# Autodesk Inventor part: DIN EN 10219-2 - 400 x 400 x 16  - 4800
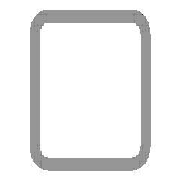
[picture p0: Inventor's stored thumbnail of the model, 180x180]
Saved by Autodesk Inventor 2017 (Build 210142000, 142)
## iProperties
IsCustomPart: 1
Created: 2017-11
Part Number: DIN EN 10219-2 - 400 x 400 x 16  - 4800
Material: Steel, Mild
Description: Cold formed welded structural hollow sections of non-alloy and fine grain structural steel
Document SubType Name: Modeling
Standard: DIN
Designer: iusti
Standard Revision: 2006-07
Standards Organization: DIN
Language: en-US
Size Designation: 400 x 400 x 16
Categories: <MemberInstance><Categories><Category DisplayName="Structural Shapes" InternalName="089c4875-fa83-4c05-b084-43b9cc11f5ed" Mnemonic="GRDR"><CategoryParameter Dis
Stock Number: 400 x 400 x 16
Density: 7.85 g/cm^3
Appearance: Semi-Polished
Mass: 884622 g
Surface Area: 141333 cm^2
Volume: 112691 cm^3
_CCFamilyMember: 142
_CCFamilyDisplayName: DIN EN 10219-2 (Square Hollow Section - Cold Formed) - Cold formed welded structural hollow sections of non-alloy and fine grain structural steel
_FrameMemberDoc: Frame Member File
_Version: 15.0.0
_GetPNFromCC: 1
G_L: 4800.000 mm
G_W: 400.000 mm
G_H: 400.000 mm
+64C0199E-E4A6-42EE-BAB6-C57CBAF8A212+CUTDETAIL1: Cut
Author: iusti
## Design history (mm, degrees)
node "Start plane"
node "End plane"
sketch "Sketch"
  geometry: L1 (-200, -152)-(-200, 152); L2 (-152, 200)-(152, 200); L3 (200, 152)-(200, -152); L4 (152, -200)-(-152, -200); L5 (-152, 184)-(152, 184); L6 (184, 152)-(184, -152); L7 (152, -184)-(-152, -184); L8 (-184, -152)-(-184, 152); L9 (0, 293.918)-(0, -293.918) reference; L10 (-293.918, 0)-(293.918, 0) reference; A1 r 48 centre (-152, -152) between (-200, -152) and (-152, -200); A2 r 48 centre (-152, 152) between (-152, 200) and (-200, 152); A3 r 48 centre (152, 152) between (200, 152) and (152, 200); A4 r 48 centre (152, -152) between (152, -200) and (200, -152); A5 r 32 centre (-152, 152) between (-152, 184) and (-184, 152); A6 r 32 centre (152, 152) between (184, 152) and (152, 184); A7 r 32 centre (152, -152) between (152, -184) and (184, -152); A8 r 32 centre (-152, -152) between (-184, -152) and (-152, -184)
  constraints: 16 end point, 16 point on circle, 8 centre point, 8 tangent, 4 parallel, 3 equal radius, 2 perpendicular, 7 other
  dimensions: "d7" = 48 radius of A1 (= G_IR); "d10" = 400 distance between parallel lines of L2 L4 (= G_H); "d11" = 400 distance between parallel lines of L1 L3 (= G_W); "d12" = 16 distance between parallel lines of L3 L6 (= G_T); "d15" = 200 distance between parallel lines of L2 L10 (= 0.5 x d10); "d16" = 200 distance between parallel lines of L9 L3 (= 0.5 x d11)
extrude "Body" new body sketch "Sketch" stored distance "d3" = 4800 (= G_L); taper "d4" = 0 deg
node "Driven Length"
  sketch "Sketch3"
    geometry: L1 (0, 0)-(10, 0) reference
    constraints: 2 end point, 1 horizontal
  workplane "Work Plane3"
  sketch "Sketch4"
    geometry: L1 (-2, 0)-(12, 0) reference; L2 (-2, 4800)-(12, 4800) reference
    dimensions: "d18" = 4800 distance between parallel lines of L1 L2 (derived)
workplane "Work Plane4"
split "Split1"
body "Solid1"
other parameters: "G_W" = 400 [user parameter; used in 1 equation term], "G_H" = 400 [user parameter; used in 1 equation term], "G_T" = 16 [user parameter; used in 1 equation term], "G_IR" = 48 [user parameter; used in 1 equation term], "G_L" = 4800 (= d18) [user parameter; used in 1 equation term], "G_OFFSET_START" = 0 [user parameter; used in 1 equation term], "d13" = 0 (computed from G_OFFSET_START), "d17" = 90 deg
